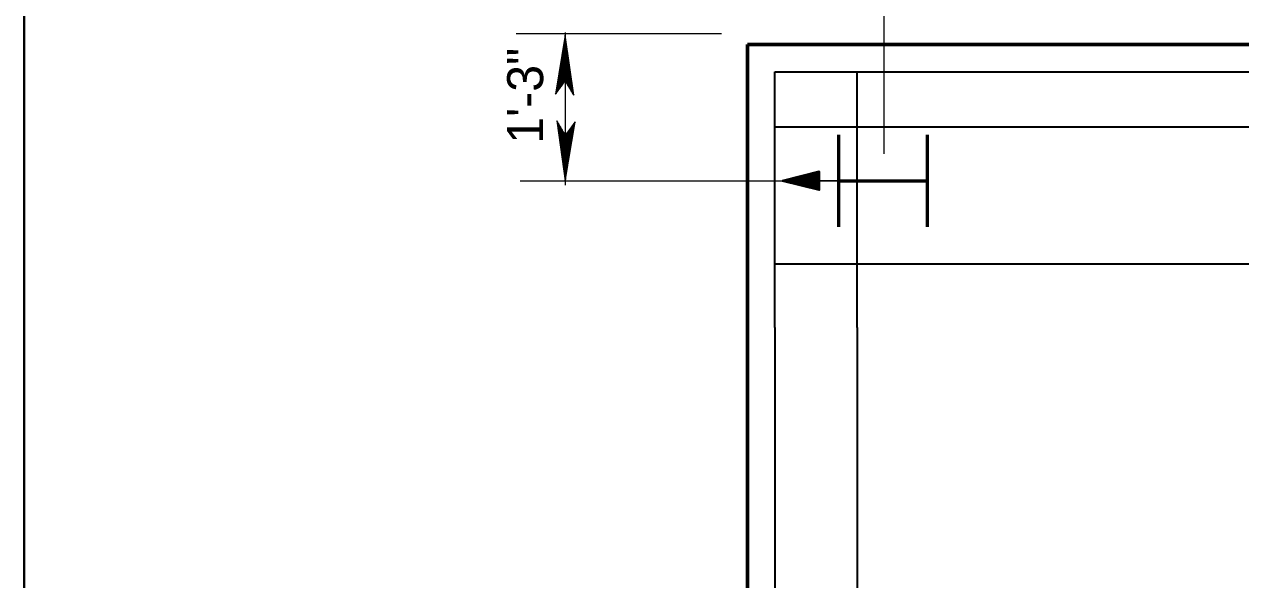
# Model space of a CAD drawing. Extents: x 144 to 252, y 360 to 425.
# Drawn here: x 149.81 to 160.9, y 374.91 to 379.97 of the extents above; entities that cross this region are included whole.
import ezdxf
from ezdxf.enums import TextEntityAlignment as Align

# ---------------------------------------------------------------- set-up
doc = ezdxf.new("R2010")
doc.units = 0
doc.header["$LTSCALE"] = 0.13
for name, color, linetype, lineweight in [('1', 7, 'Continuous', 40), ('10', 7, 'Continuous', 35), ('16', 7, 'Continuous', 13), ('3', 7, 'Continuous', 13), ('9', 7, 'Continuous', 25)]:
    doc.layers.add(name, color=color, linetype=linetype, lineweight=lineweight)

msp = doc.modelspace()

# ---------------------------------------------------------------- linework, layer by layer
at = {"layer": '1', "lineweight": 60}
for p, q in [((156.4041, 369.7844), (156.4041, 379.7844)), ((156.4041, 379.7844), (180.4041, 379.7844)), ((156.4041, 379.7844), (180.4041, 379.7844)), ((156.4041, 379.7844), (180.4041, 379.7844)), ((156.4041, 379.7844), (180.4041, 379.7844)), ((156.4041, 377.2068), (156.4041, 379.7844)), ((156.4041, 377.2068), (156.4041, 379.7844)), ((156.4041, 377.5272), (156.4041, 375.7844)), ((156.4041, 376.5865), (156.4041, 371.7844)), ((156.4041, 375.1273), (156.4041, 376.5865))]:
    msp.add_line(p, q, dxfattribs=at)
at = {"layer": '1', "lineweight": 35}
for p, q in [((156.6541, 379.5344), (168.3923, 379.5344)), ((156.6541, 377.2068), (156.6541, 379.5344)), ((157.4041, 377.2068), (157.4041, 379.5344)), ((156.6541, 379.0344), (168.3923, 379.0344)), ((156.6541, 377.7844), (168.4097, 377.7844)), ((156.6541, 377.2068), (156.6541, 373.7844)), ((157.4041, 377.2068), (157.4041, 373.7844))]:
    msp.add_line(p, q, dxfattribs=at)
at = {"layer": '1', "lineweight": 53}
for p, q in [((157.2358, 378.1227), (157.2358, 378.9623)), ((158.0442, 378.1228), (158.0442, 378.9624)), ((157.2358, 378.5426), (158.0442, 378.5426))]:
    msp.add_line(p, q, dxfattribs=at)
at = {"layer": '1', "lineweight": 25}
msp.add_line((157.2358, 378.5426), (156.7358, 378.5426), dxfattribs=at)
at = {"layer": '1'}
msp.add_lwpolyline([(250.3172, 361.9183), (250.3172, 423.9913), (149.8112, 423.9913), (149.8112, 361.9183), (230.3642, 361.9183)], dxfattribs=at)
at = {"layer": '1', "lineweight": 60}
msp.add_lwpolyline([(156.4041, 379.7844), (180.4041, 379.7844), (180.4041, 369.7844)], dxfattribs=at)
at = {"layer": '10'}
for p, q in [((157.058, 378.5422), (156.7227, 378.5422)), ((156.8741, 378.5272), (157.058, 378.5196)), ((156.8742, 378.5336), (157.058, 378.5258)), ((157.058, 378.5322), (156.8743, 378.5398)), ((156.8745, 378.5461), (157.058, 378.5384)), ((157.058, 378.4944), (156.8854, 378.5017))]:
    msp.add_line(p, q, dxfattribs=at)
for points in [[(157.058, 378.6257), (157.058, 378.4588), (156.7227, 378.5421)], [(157.058, 378.6257), (156.7227, 378.5421), (157.058, 378.6257)]]:
    msp.add_lwpolyline(points, dxfattribs=at)
msp.add_lwpolyline([(156.7227, 378.5421), (157.058, 378.6257), (157.058, 378.4588), (157.058, 378.6257)], close=True, dxfattribs=at)
at = {"layer": '3'}
for p, q in [((157.6499, 378.7893), (157.6499, 381.0482)), ((156.1668, 379.8812), (154.2952, 379.8812)), ((154.7432, 379.8701), (154.6539, 379.3324)), ((154.7425, 379.8557), (154.6562, 379.3357)), ((154.7425, 379.8448), (154.6586, 379.3389)), ((154.7425, 379.8304), (154.6617, 379.3432)), ((154.7425, 379.8177), (154.6644, 379.3469)), ((154.8174, 379.3273), (154.7425, 379.8557)), ((154.8154, 379.3308), (154.7425, 379.8448)), ((154.8127, 379.3354), (154.7425, 379.8304)), ((154.8103, 379.3395), (154.7425, 379.8177)), ((154.8103, 379.3395), (154.7425, 379.8177)), ((154.7432, 379.4547), (154.7432, 379.8701)), ((154.8209, 379.3213), (154.7432, 379.8701)), ((154.7444, 378.504), (154.7444, 379.8942)), ((154.7425, 379.8063), (154.6668, 379.3502)), ((154.7425, 379.7919), (154.67, 379.3545)), ((154.7425, 379.7792), (154.6728, 379.3582)), ((154.7425, 379.7654), (154.6757, 379.3623)), ((154.7425, 379.7516), (154.6787, 379.3664)), ((154.7425, 379.7383), (154.6815, 379.3703)), ((154.7425, 379.7244), (154.6845, 379.3744)), ((154.7425, 379.7118), (154.6872, 379.3782)), ((154.7425, 379.7004), (154.6897, 379.3816)), ((154.8082, 379.3432), (154.7425, 379.8063)), ((154.8055, 379.3477), (154.7425, 379.7919)), ((154.8031, 379.3518), (154.7425, 379.7792)), ((154.8006, 379.3562), (154.7425, 379.7654)), ((154.798, 379.3607), (154.7425, 379.7516)), ((154.7955, 379.3649), (154.7425, 379.7383)), ((154.7928, 379.3694), (154.7425, 379.7244)), ((154.7906, 379.3734), (154.7425, 379.7118)), ((154.7883, 379.3772), (154.7425, 379.7004)), ((154.7425, 379.6848), (154.693, 379.3862)), ((154.7425, 379.6709), (154.696, 379.3902)), ((154.742, 379.6529), (154.6991, 379.3945)), ((154.742, 379.639), (154.7021, 379.3987)), ((154.742, 379.6258), (154.7049, 379.4025)), ((154.7425, 379.6167), (154.7077, 379.4062)), ((154.7425, 379.6047), (154.7103, 379.4098)), ((154.7425, 379.5909), (154.7132, 379.4139)), ((154.7787, 379.3938), (154.742, 379.6529)), ((154.7761, 379.3982), (154.742, 379.639)), ((154.7736, 379.4024), (154.742, 379.6258)), ((154.7855, 379.3822), (154.7425, 379.6848)), ((154.7828, 379.3866), (154.7425, 379.6709)), ((154.7728, 379.4039), (154.7425, 379.6167)), ((154.7705, 379.4078), (154.7425, 379.6047)), ((154.7678, 379.4122), (154.7425, 379.5909)), ((154.7806, 379.3906), (154.7436, 379.6513)), ((154.7425, 379.5752), (154.7165, 379.4186)), ((154.7425, 379.5627), (154.7192, 379.4222)), ((154.7425, 379.5494), (154.7221, 379.4262)), ((154.7425, 379.5374), (154.7248, 379.4298)), ((154.7425, 379.5229), (154.7277, 379.434)), ((154.7425, 379.5091), (154.7308, 379.4382)), ((154.7425, 379.4964), (154.7335, 379.4418)), ((154.7425, 379.4832), (154.7363, 379.4457)), ((154.765, 379.4172), (154.7425, 379.5752)), ((154.7626, 379.4213), (154.7425, 379.5627)), ((154.7601, 379.4256), (154.7425, 379.5494)), ((154.7578, 379.4294), (154.7425, 379.5374)), ((154.7552, 379.4341), (154.7425, 379.5229)), ((154.7526, 379.4385), (154.7425, 379.5091)), ((154.7502, 379.4426), (154.7425, 379.4964)), ((154.6539, 379.3324), (154.743, 379.4549)), ((154.7425, 379.4717), (154.7387, 379.4492)), ((154.7425, 379.4616), (154.741, 379.4522)), ((154.7456, 379.4505), (154.7425, 379.4717)), ((154.743, 379.4549), (154.8209, 379.3213)), ((154.7472, 379.4478), (154.7436, 379.4729)), ((154.6654, 379.0897), (154.7432, 378.5409)), ((154.7433, 378.9561), (154.6654, 379.0897)), ((154.6689, 379.0837), (154.7438, 378.5553)), ((154.6709, 379.0802), (154.7438, 378.5662)), ((154.6736, 379.0756), (154.7438, 378.5806)), ((154.676, 379.0715), (154.7438, 378.5933)), ((154.676, 379.0715), (154.7438, 378.5933)), ((154.6782, 379.0678), (154.7438, 378.6047)), ((154.6808, 379.0632), (154.7438, 378.6191)), ((154.6832, 379.0592), (154.7438, 378.6318)), ((154.6857, 379.0548), (154.7438, 378.6456)), ((154.6883, 379.0503), (154.7438, 378.6594)), ((154.6908, 379.0461), (154.7438, 378.6727)), ((154.6935, 379.0416), (154.7438, 378.6866)), ((154.6958, 379.0376), (154.7438, 378.6992)), ((154.698, 379.0338), (154.7438, 378.7106)), ((154.7432, 378.5409), (154.8324, 379.0786)), ((154.8324, 379.0786), (154.7433, 378.9561)), ((154.7438, 378.5553), (154.8301, 379.0753)), ((154.7438, 378.5662), (154.8278, 379.0721)), ((154.7438, 378.5806), (154.8246, 379.0678)), ((154.7438, 378.5933), (154.8219, 379.0641)), ((154.7438, 378.6047), (154.8195, 379.0607)), ((154.7438, 378.6191), (154.8163, 379.0565)), ((154.7438, 378.6318), (154.8136, 379.0528)), ((154.7438, 378.6456), (154.8107, 379.0487)), ((154.7438, 378.6594), (154.8077, 379.0446)), ((154.7438, 378.6727), (154.8048, 379.0407)), ((154.7438, 378.6866), (154.8018, 379.0366)), ((154.7008, 379.0288), (154.7438, 378.7262)), ((154.7035, 379.0244), (154.7438, 378.7401)), ((154.7057, 379.0204), (154.7428, 378.7597)), ((154.7077, 379.0172), (154.7443, 378.7581)), ((154.7103, 379.0128), (154.7443, 378.772)), ((154.7127, 379.0086), (154.7443, 378.7852)), ((154.7136, 379.0071), (154.7438, 378.7942)), ((154.7158, 379.0032), (154.7438, 378.8062)), ((154.7185, 378.9987), (154.7438, 378.8201)), ((154.7213, 378.9937), (154.7438, 378.8357)), ((154.7237, 378.9897), (154.7438, 378.8483)), ((154.7262, 378.9854), (154.7438, 378.8616)), ((154.7285, 378.9816), (154.7438, 378.8736)), ((154.7312, 378.9769), (154.7438, 378.8881)), ((154.7337, 378.9725), (154.7438, 378.9019)), ((154.7361, 378.9684), (154.7438, 378.9146)), ((154.7392, 378.9632), (154.7428, 378.9381)), ((154.7407, 378.9605), (154.7438, 378.9393)), ((154.7432, 378.9563), (154.7432, 378.5409)), ((154.7438, 378.6992), (154.7992, 379.0328)), ((154.7438, 378.7106), (154.7967, 379.0294)), ((154.7438, 378.7262), (154.7933, 379.0248)), ((154.7438, 378.7401), (154.7903, 379.0207)), ((154.7438, 378.7942), (154.7787, 379.0048)), ((154.7438, 378.8062), (154.7761, 379.0012)), ((154.7438, 378.8201), (154.7731, 378.9971)), ((154.7438, 378.8357), (154.7698, 378.9924)), ((154.7438, 378.8483), (154.7671, 378.9887)), ((154.7438, 378.8616), (154.7643, 378.9848)), ((154.7438, 378.8736), (154.7616, 378.9812)), ((154.7438, 378.8881), (154.7586, 378.977)), ((154.7438, 378.9019), (154.7556, 378.9728)), ((154.7438, 378.9146), (154.7528, 378.9692)), ((154.7438, 378.9278), (154.75, 378.9652)), ((154.7438, 378.9393), (154.7476, 378.9618)), ((154.7438, 378.9494), (154.7453, 378.9588)), ((154.7443, 378.7581), (154.7873, 379.0165)), ((154.7443, 378.772), (154.7842, 379.0123)), ((154.7443, 378.7852), (154.7814, 379.0085)), ((157.0496, 378.5392), (154.3306, 378.5392))]:
    msp.add_line(p, q, dxfattribs=at)
at = {"layer": '9'}
for p, q in [((156.9312, 378.594), (157.058, 378.5888)), ((156.9528, 378.5994), (157.058, 378.5951)), ((156.9743, 378.6048), (157.058, 378.6013)), ((156.9959, 378.6102), (157.058, 378.6076)), ((157.0176, 378.6156), (157.058, 378.6139)), ((157.0392, 378.621), (157.058, 378.6202)), ((156.7334, 378.5394), (156.8742, 378.5336)), ((156.7368, 378.5456), (156.8743, 378.5398)), ((156.7584, 378.551), (156.8745, 378.5461)), ((156.7638, 378.5319), (156.8741, 378.5272)), ((156.78, 378.5563), (156.8747, 378.5524)), ((156.7943, 378.5243), (156.8739, 378.521)), ((156.8016, 378.5617), (156.8748, 378.5587)), ((156.8232, 378.5671), (156.875, 378.565)), ((156.8246, 378.5168), (156.8738, 378.5147)), ((156.8448, 378.5725), (156.8752, 378.5712)), ((156.855, 378.5092), (156.8736, 378.5084)), ((156.8664, 378.5778), (156.8753, 378.5775)), ((156.8736, 378.5084), (157.058, 378.5007)), ((156.8738, 378.5147), (157.058, 378.507)), ((156.8739, 378.521), (157.058, 378.5133)), ((156.8747, 378.5524), (157.058, 378.5447)), ((156.8748, 378.5587), (157.058, 378.551)), ((156.875, 378.565), (157.058, 378.5573)), ((156.8752, 378.5712), (157.058, 378.5636)), ((156.8753, 378.5775), (157.058, 378.5699)), ((156.888, 378.5832), (157.058, 378.5762)), ((156.9096, 378.5887), (157.058, 378.5824)), ((156.9158, 378.4941), (157.058, 378.4881)), ((156.9462, 378.4865), (157.058, 378.4818)), ((156.9766, 378.479), (157.058, 378.4756)), ((157.007, 378.4714), (157.058, 378.4692)), ((157.0373, 378.4638), (157.058, 378.463))]:
    msp.add_line(p, q, dxfattribs=at)
at = {"layer": '9', "lineweight": 40}
msp.add_lwpolyline([(156.7227, 378.5421), (157.058, 378.6257), (157.058, 378.4588)], close=True, dxfattribs=at)

# ---------------------------------------------------------------- texts
at = {"layer": '16'}
msp.add_text('1\'-3"', height=0.3281, rotation=90, dxfattribs=at).set_placement((154.5412, 379.3172), align=Align.CENTER)

doc.saveas('drawing.dxf')
